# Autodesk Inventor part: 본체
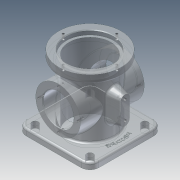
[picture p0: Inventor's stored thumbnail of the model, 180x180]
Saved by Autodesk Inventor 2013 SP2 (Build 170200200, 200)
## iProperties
Created: 2021-03
Part Number: 본체
Material: 유리
Document SubType Name: Modeling
Designer: kumcom8
Density: 2.18 g/cm^3
Mass: 670.741 g
Surface Area: 863.886 cm^2
Volume: 307.679 cm^3
Author: kumcom8
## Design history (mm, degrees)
sketch "스케치1"
  geometry: C1 r 38 at (0, 0); 1 further point
  constraints: 1 centre point, 1 coincident
  dimensions: "d0" = 76 diameter of C1
extrude "돌출1" new body sketch "스케치1" distance "d1" = 111; taper "d2" = 0 deg
sketch "스케치2"
  geometry: C1 r 38 at (0, 0) reference; C2 r 49 at (0, 0)
  constraints: 1 centre point, 1 coincident
  dimensions: "d3" = 98 diameter of C2
extrude "돌출2" join sketch "스케치2" distance "d4" = 13; taper "d5" = 0 deg
sketch "스케치3"
  geometry: L1 (-57, 57)-(57, 57); L2 (57, 57)-(57, -57); L3 (57, -57)-(-57, -57); L4 (-57, -57)-(-57, 57); L5 (-57, 57)-(57, -57); L6 (57, 57)-(-57, -57); C1 r 38 at (0, 0) reference
  constraints: 12 end point, 2 midpoint, 2 parallel, 1 horizontal, 1 perpendicular
  dimensions: "d6" = 114 distance of L2.end L3.end; "d7" = 114 distance of L1.end L2.end
extrude "돌출3" join sketch "스케치3" distance "d8" = 10; taper "d9" = 0 deg
sketch "스케치4"
  geometry: L1 (0, 57)-(0, -57) reference; L2 (0, 0)-(54, 0); C1 r 35 at (54, 0)
  constraints: 2 end point, 1 centre point, 1 coincident, 1 perpendicular
  dimensions: "d10" = 54 distance of L2.start L2.end; "d11" = 70 diameter of C1
extrude "돌출4" join sketch "스케치4" stored distance "d12" = 100; taper "d13" = 0 deg
sketch "스케치5"
  geometry: C1 r 35 at (0, 0) reference; C2 r 24 at (0, 0); 1 further point
  constraints: 1 centre point, 1 coincident
  dimensions: "d14" = 48 diameter of C2
extrude "돌출5" cut sketch "스케치5" stored distance "d15" = 100; taper "d16" = 0 deg
sketch "스케치6"
  geometry: C1 r 49 at (0, 0) reference; C2 r 37 at (0, 0)
  constraints: 1 centre point, 1 coincident
  dimensions: "d17" = 74 diameter of C2
extrude "돌출6" cut sketch "스케치6" distance "d18" = 7; taper "d19" = 0 deg
sketch "스케치7"
  geometry: C1 r 37 at (0, 0) reference; C2 r 33 at (0, 0)
  constraints: 1 centre point, 1 coincident
  dimensions: "d20" = 66 diameter of C2
extrude "돌출7" cut sketch "스케치7" stored distance "d21" = 7; taper "d22" = 0 deg
fillet "모깎기1" dims "d23" = 14
sketch "스케치8"
  geometry: L1 (0, 0)-(0, 42); C1 r 49 at (0, 0) reference; 1 further point
  constraints: 2 end point, 1 coincident, 1 vertical
  dimensions: "d24" = 42 distance of L1.start L1.end
hole "구멍1" sketch "스케치8" at (0, 42) diameter "d25" = 3.242; stored, may be unused: countersink angle "d29" = 90 deg, drill point angle "d31" = 118 deg; dims "d26" = 6, "d27" = 4, "d28" = 2, "d30" = 8
sketch "스케치9"
  geometry: L1 (0, 0)-(0, 31); C1 r 35 at (0, 0) reference; 2 further points
  constraints: 2 end point, 1 coincident, 1 vertical
  dimensions: "d35" = 31 distance of L1.start L1.end
hole "구멍2" sketch "스케치9" at (0, 31) diameter "d36" = 3.242; stored, may be unused: countersink angle "d40" = 90 deg, drill point angle "d42" = 118 deg; dims "d37" = 6, "d38" = 4, "d39" = 2, "d41" = 8
sketch "스케치10"
  geometry: C1 r 5 at (-43, 43); C2 r 5 at (43, 43); C3 r 5 at (-43, -43); C4 r 5 at (43, -43); A1 r 14 centre (43, 43) between (57, 43) and (43, 57) reference; A2 r 14 centre (-43, 43) between (-43, 57) and (-57, 43) reference; A3 r 14 centre (-43, -43) between (-57, -43) and (-43, -57) reference; A4 r 14 centre (43, -43) between (43, -57) and (57, -43) reference
  constraints: 4 centre point, 4 coincident
  dimensions: "d46" = 10 diameter of C1; "d47" = 10 diameter of C2; "d48" = 10 diameter of C3; "d49" = 10 diameter of C4
extrude "돌출8" cut sketch "스케치10" stored distance "d50" = 7; taper "d51" = 0 deg
node "작업 평면2"
sketch "스케치14"
  geometry: L1 (-50, 89)-(-50, 19) reference; L2 (50, 19)-(50, 89) reference; L3 (-50, 54)-(50, 54); L4 (0, 77)-(0, 77); L5 (7, 70)-(7, 41); L6 (0, 34)-(0, 34); L7 (-7, 41)-(-7, 70); A1 r 7 centre (0, 70) between (7, 70) and (0, 77); A2 r 7 centre (0, 70) between (0, 77) and (-7, 70); A3 r 7 centre (0, 41) between (-7, 41) and (0, 34); A4 r 7 centre (0, 41) between (0, 34) and (7, 41); 6 further points
  constraints: 10 end point, 8 point on circle, 8 tangent, 6 point on line, 4 centre point, 4 midpoint, 3 equal radius, 2 parallel, 1 horizontal, 1 perpendicular, 1 vertical alignment
  dimensions: "d57" = 14 distance of point (7, 34) point (-7, 34); "d58" = 43 distance of point (7, 77) point (7, 34); "d59" = 20 distance of point (0, 54) point (0, 34); "d60" = 7 radius of A1
extrude "돌출9" join sketch "스케치14" stored distance "d61" = 7; taper "d62" = 15 deg
sketch "스케치15"
  geometry: A1 r 7 centre (0, 70) between (7, 70) and (-7, 70) reference; A2 r 7 centre (0, 41) between (-7, 41) and (7, 41) reference; 3 further points
  constraints: 2 coincident
hole "구멍3" sketch "스케치15" at (0, 70), (0, 41) diameter "d63" = 4.134; stored, may be unused: countersink angle "d67" = 90 deg, drill point angle "d69" = 118 deg; dims "d64" = 8, "d65" = 4, "d66" = 2, "d68" = 10
sketch "스케치16"
  geometry: C1 r 38 at (0, 0) reference; C2 r 50 at (0, 0)
  constraints: 1 centre point, 1 coincident, 1 other
  dimensions: "d70" = 100 diameter of C2
feature "엠보싱1" sketch "스케치16" dims "d71" = 0.5, "d72" = 0
chamfer "모따기1" distance "d73" = 1; stored, may be unused: second distance "d74" = 2, angle "d75" = 45 deg
fillet "모깎기2" dims "d76" = 3
fillet "모깎기3" dims "d77" = 3
fillet "모깎기4" dims "d78" = 3
fillet "모깎기5" dims "d79" = 3
fillet "모깎기6" dims "d80" = 3
node "솔리드1"
pattern_circular "원형 패턴1" dims angle "d33" = 360 deg
pattern_circular "원형 패턴2" dims angle "d44" = 360 deg
mirror "대칭1"
other parameters: "d56" = 55
